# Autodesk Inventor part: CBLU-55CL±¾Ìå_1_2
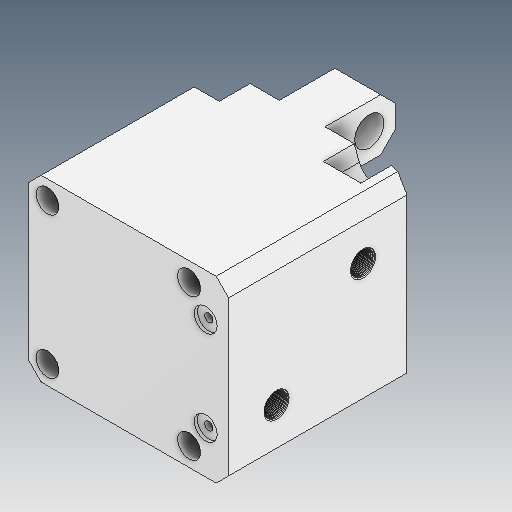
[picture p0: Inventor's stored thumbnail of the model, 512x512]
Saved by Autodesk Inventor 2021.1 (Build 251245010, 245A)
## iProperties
Created: 2021-05
Part Number: CBLU-55CL±¾Ìå_1_2
Material: Ogólny
Document SubType Name: Modeling
Designer: user
Density: 1 g/cm^3
Appearance: Domyślna
Author: user
Revision Number: ÈÎºÎ
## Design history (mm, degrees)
feature "ÊäÈë1"
feature "ÇÐ³ý-À­Éì1" [ÊäÈë]
node "Bryła1"
node "Bryła2"
